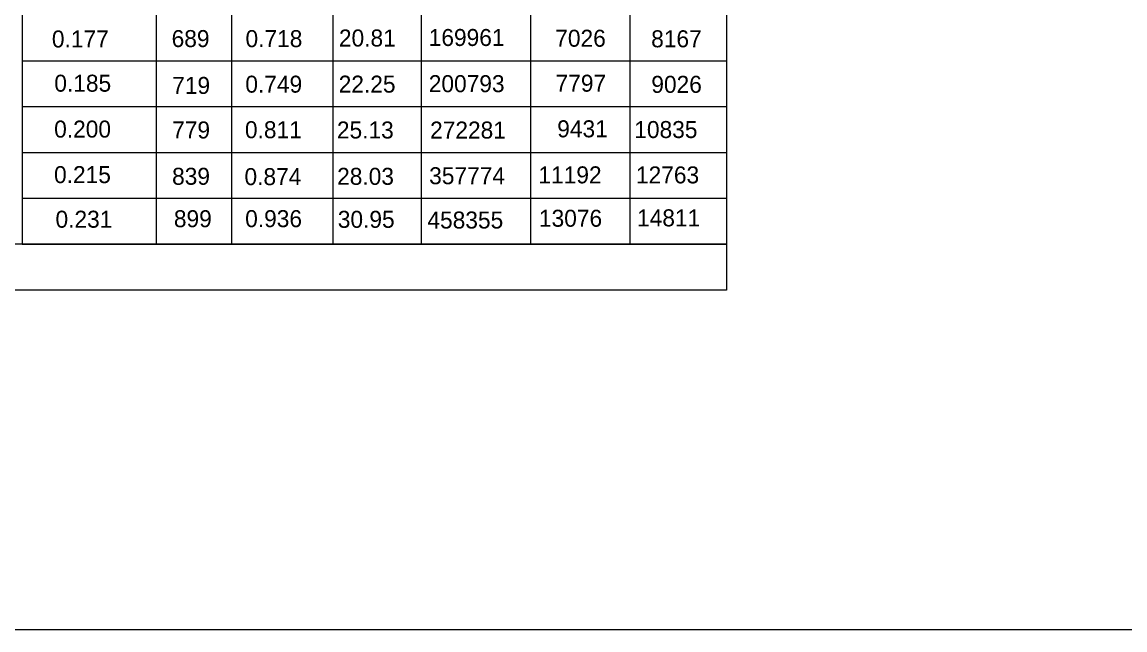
# Model space of a CAD drawing. Extents: x 635698 to 639877, y 296617 to 300175.
# Drawn here: x 639162 to 639356.8, y 299460.8 to 299568.1 of the extents above; entities that cross this region are included whole.
import ezdxf

# ---------------------------------------------------------------- set-up
doc = ezdxf.new("R2010")
doc.units = 0
for name, color, linetype in [('1', 7, 'Continuous'), ('2', 7, 'Continuous'), ('3', 7, 'Continuous')]:
    doc.layers.add(name, color=color, linetype=linetype)

msp = doc.modelspace()

# ---------------------------------------------------------------- linework, layer by layer
at = {"layer": '1'}
for p, q in [((639286.46, 299670.74), (639286.46, 299520.81)), ((639162.02, 299660.17), (639162.02, 299528.89)), ((639185.67, 299652.58), (639185.67, 299528.89)), ((639199.02, 299652.58), (639199.02, 299528.89)), ((639216.88, 299652.58), (639216.88, 299528.89)), ((639232.53, 299652.58), (639232.53, 299528.89)), ((639251.81, 299652.58), (639251.81, 299528.89)), ((639269.36, 299652.58), (639269.36, 299528.89)), ((639286.46, 299561.21), (639162.02, 299561.21)), ((639286.46, 299553.13), (639162.02, 299553.13)), ((639286.46, 299545.04), (639162.02, 299545.04)), ((639286.46, 299536.96), (639162.02, 299536.96)), ((639286.46, 299528.89), (639018.88, 299528.89)), ((639286.46, 299528.87), (639162.02, 299528.87)), ((639286.46, 299520.81), (638876.19, 299520.81))]:
    msp.add_line(p, q, dxfattribs=at)
at = {"layer": '2'}
msp.add_line((639628.3, 299460.8), (638842.3, 299460.8), dxfattribs=at)

# ---------------------------------------------------------------- texts
at = {"layer": '3'}
for s, p in [('0.177', (639167.28, 299563.63)), ('689', (639188.43, 299563.7)), ('0.718', (639201.48, 299563.69)), ('20.81', (639217.98, 299563.8)), ('169961', (639233.84, 299563.89)), ('7026', (639256.19, 299563.76)), ('8167', (639273.13, 299563.66)), ('0.185', (639167.71, 299555.82)), ('0.749', (639201.45, 299555.65)), ('22.25', (639217.94, 299555.66)), ('200793', (639233.85, 299555.74)), ('7797', (639256.25, 299555.82)), ('9026', (639273.16, 299555.62)), ('719', (639188.53, 299555.43)), ('9431', (639256.54, 299547.77)), ('0.200', (639167.68, 299547.72)), ('779', (639188.52, 299547.57)), ('0.811', (639201.38, 299547.61)), ('25.13', (639217.62, 299547.56)), ('272281', (639234.08, 299547.55)), ('10835', (639270.15, 299547.64)), ('0.215', (639167.66, 299539.68)), ('839', (639188.51, 299539.39)), ('0.874', (639201.3, 299539.33)), ('28.03', (639217.66, 299539.38)), ('357774', (639233.92, 299539.49)), ('11192', (639253.22, 299539.64)), ('12763', (639270.45, 299539.63)), ('0.231', (639167.92, 299531.81)), ('899', (639188.83, 299531.9)), ('0.936', (639201.42, 299531.91)), ('30.95', (639217.78, 299531.79)), ('458355', (639233.61, 299531.67)), ('13076', (639253.31, 299531.98)), ('14811', (639270.64, 299532.05))]:
    msp.add_text(s, height=3.001, dxfattribs=at).set_placement(p)

doc.saveas('drawing.dxf')
